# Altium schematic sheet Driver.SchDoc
size A4
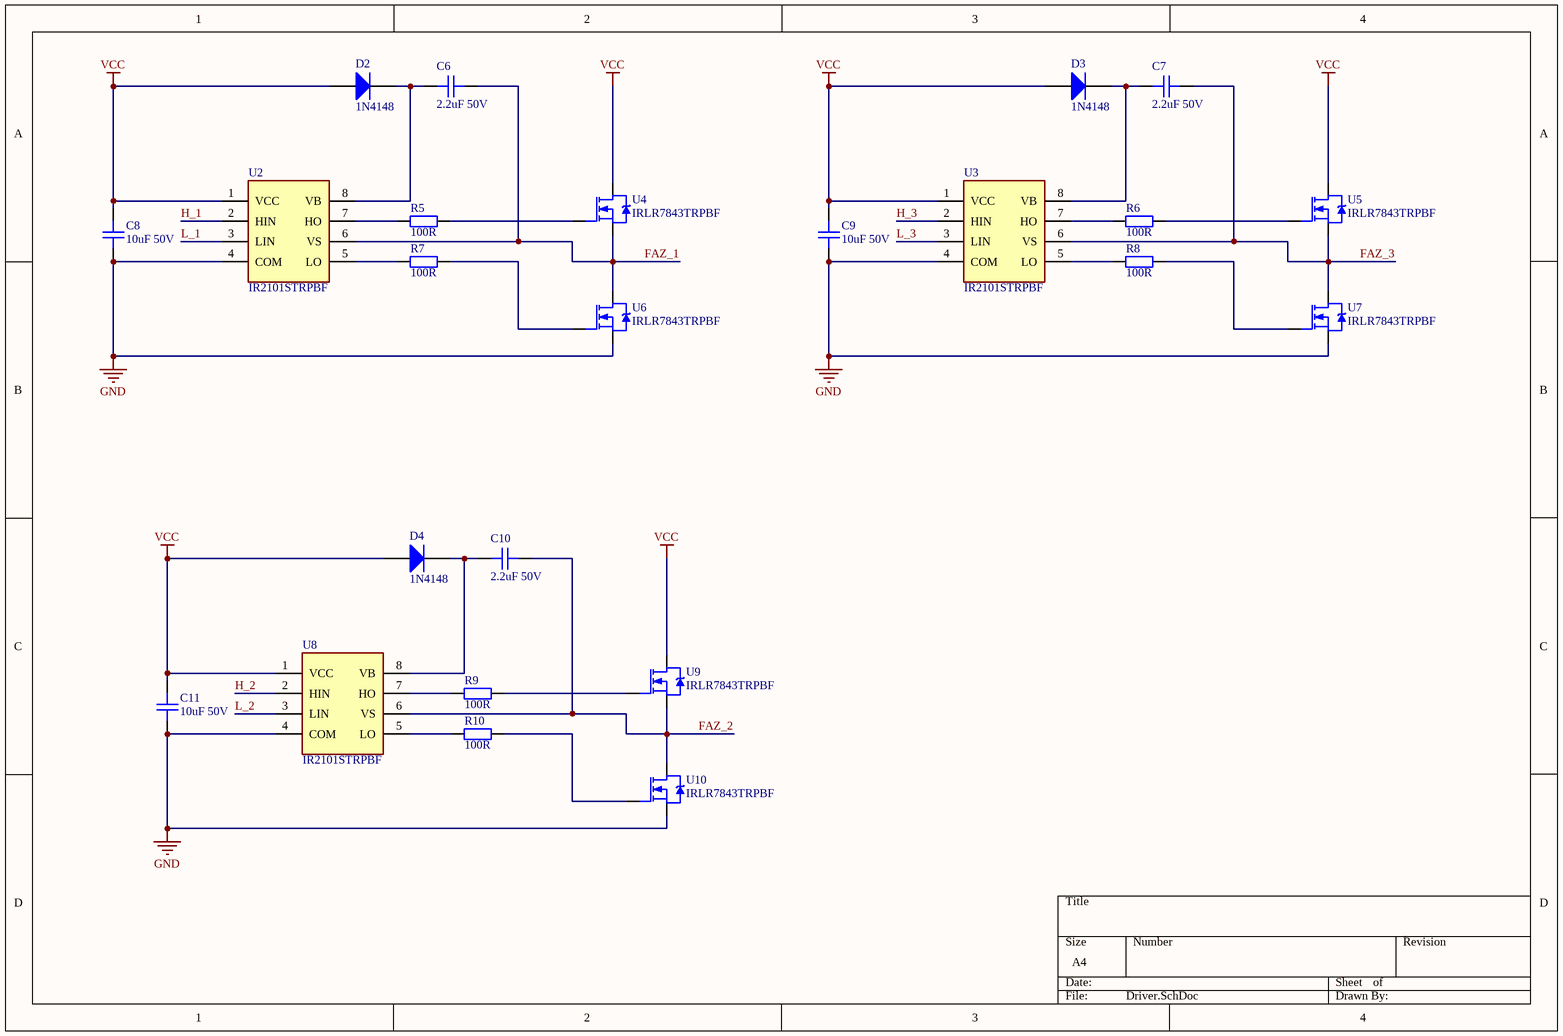
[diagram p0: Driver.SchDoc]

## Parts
C6  Deger: 2.2uF 50V  [CAP 1206/3216]  (hidden comment: CAP CER 2.2UF 50V X5R 1206)
C7  Deger: 2.2uF 50V  [CAP 1206/3216]  (hidden comment: CAP CER 2.2UF 50V X5R 1206)
C8  Deger: 10uF 50V  [CAP 1206/3216]  (hidden comment: CAP CER 10UF 50V X5R 1206)
C9  Deger: 10uF 50V  [CAP 1206/3216]  (hidden comment: CAP CER 10UF 50V X5R 1206)
C10  Deger: 2.2uF 50V  [CAP 1206/3216]  (hidden comment: CAP CER 2.2UF 50V X5R 1206)
C11  Deger: 10uF 50V  [CAP 1206/3216]  (hidden comment: CAP CER 10UF 50V X5R 1206)
D2  1N4148 Diyot  [SOD-123]  (value not drawn)
D3  1N4148 Diyot  [SOD-123]  (value not drawn)
D4  1N4148 Diyot  [SOD-123]  (value not drawn)
R5  Deger: 100R  [RES_0805]  (hidden comment: RES SMD 100 OHM 1% 1/8W 0805)
R6  Deger: 100R  [RES_0805]  (hidden comment: RES SMD 100 OHM 1% 1/8W 0805)
R7  Deger: 100R  [RES_0805]  (hidden comment: RES SMD 100 OHM 1% 1/8W 0805)
R8  Deger: 100R  [RES_0805]  (hidden comment: RES SMD 100 OHM 1% 1/8W 0805)
R9  Deger: 100R  [RES_0805]  (hidden comment: RES SMD 100 OHM 1% 1/8W 0805)
R10  Deger: 100R  [RES_0805]  (hidden comment: RES SMD 100 OHM 1% 1/8W 0805)
U2  Deger: IR2101STRPBF  [SOIC8]  (hidden comment: IC GATE DRVR HALF-BRIDGE 8SOIC)
U3  Deger: IR2101STRPBF  [SOIC8]  (hidden comment: IC GATE DRVR HALF-BRIDGE 8SOIC)
U4  Deger: IRLR7843TRPBF  [DPAK]  (hidden comment: MOSFET N-CH 30V 161A DPAK)
U5  Deger: IRLR7843TRPBF  [DPAK]  (hidden comment: MOSFET N-CH 30V 161A DPAK)
U6  Deger: IRLR7843TRPBF  [DPAK]  (hidden comment: MOSFET N-CH 30V 161A DPAK)
U7  Deger: IRLR7843TRPBF  [DPAK]  (hidden comment: MOSFET N-CH 30V 161A DPAK)
U8  Deger: IR2101STRPBF  [SOIC8]  (hidden comment: IC GATE DRVR HALF-BRIDGE 8SOIC)
U9  Deger: IRLR7843TRPBF  [DPAK]  (hidden comment: MOSFET N-CH 30V 161A DPAK)
U10  Deger: IRLR7843TRPBF  [DPAK]  (hidden comment: MOSFET N-CH 30V 161A DPAK)

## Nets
GND: C8.1 C9.1 C11.1 U2.4(COM) U3.4(COM) U6.3(S) U7.3(S) U8.4(COM) U10.3(S)
VCC: C8.2 C9.2 C11.2 D2.1(A) D3.1(A) D4.1(A) U2.1(VCC) U3.1(VCC) U4.4(D) U5.4(D) U8.1(VCC) U9.4(D)
FAZ_1: C6.2 U2.6(VS) U4.3(S) U6.4(D)
FAZ_2: C10.2 U8.6(VS) U9.3(S) U10.4(D)
FAZ_3: C7.2 U3.6(VS) U5.3(S) U7.4(D)
H_1: U2.2(HIN)
H_2: U8.2(HIN)
H_3: U3.2(HIN)
L_1: U2.3(LIN)
L_2: U8.3(LIN)
L_3: U3.3(LIN)
NetC6_1: C6.1 D2.2(K) U2.8(VB)
NetC7_1: C7.1 D3.2(K) U3.8(VB)
NetC10_1: C10.1 D4.2(K) U8.8(VB)
NetR5_1: R5.1 U2.7(HO)
NetR5_2: R5.2 U4.1(G)
NetR6_1: R6.1 U3.7(HO)
NetR6_2: R6.2 U5.1(G)
NetR7_1: R7.1 U2.5(LO)
NetR7_2: R7.2 U6.1(G)
NetR8_1: R8.1 U3.5(LO)
NetR8_2: R8.2 U7.1(G)
NetR9_1: R9.1 U8.7(HO)
NetR9_2: R9.2 U9.1(G)
NetR10_1: R10.1 U8.5(LO)
NetR10_2: R10.2 U10.1(G)

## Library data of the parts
C6 C7 C10 = 2.2uF 50V 1206: 2.2µF ±10% 50V Ceramic Capacitor X5R 1206 (3216 Metric); Cins: Kondansator; Uretici Kodu: CL31A225KBHNNNE; Kılıf: 1206; -Sicaklik: -55; +Sicaklik: +85; Lehim Yöntemi: SMD
C8 C9 C11 = 10uF 50V 1206: 10µF ±10% 50V Ceramic Capacitor X5R 1206 (3216 Metric); Cins: Kondansator; Uretici Kodu: CL31A106KBHNNNE; Kılıf: 1206; -Sicaklik: -55; +Sicaklik: +125; Lehim Yöntemi: SMD
D2-D4 = 1N4148: DIODE GEN PURP 100V 150MA SOD123; Uretici Kodu: 1N4148W-TP; -Sicaklik: -65; +Sicaklik: +150; Lehim Yöntemi: SMD
R5-R10 = 100R 0805: 100 Ohms ±1% 0.125W, 1/8W Chip Resistor 0805 (2012 Metric) Moisture Resistant Thick Film; Cins: Direnc; Uretici Kodu: RC0805FR-07100RL; Kılıf: 0805; -Sicaklik: -55; +Sicaklik: +155
U2 U3 U8 = IR2101: Half-Bridge Gate Driver IC Non-Inverting 8-SOIC; -Sicaklik: -40; +Sicaklik: +150; Lehim Yöntemi: SMD
U4-U7 U9 U10 = IRLR7843: N-Channel 30V 161A (Tc) 140W (Tc) Surface Mount D-Pak; Kılıf: DPAK(TO-252-3); -Sicaklik: -55; +Sicaklik: +175; Lehim Yöntemi: SMD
